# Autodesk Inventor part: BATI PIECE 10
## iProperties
Created: 2004-11
Part Number: BATI PIECE 10
Document SubType Name: Modeling
Designer: Bruno
Manufacturer: Standard
Standards Organization: Custom
Author: Bruno
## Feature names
1. Base1
